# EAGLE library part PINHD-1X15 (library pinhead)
PIN HEADER
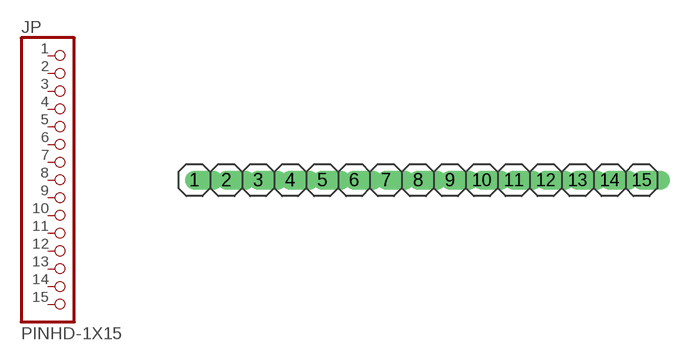
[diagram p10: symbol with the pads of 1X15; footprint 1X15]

Designator prefix JP

## PINHD-1X15  [1X15]
1  1  pas
2  2  pas
3  3  pas
4  4  pas
5  5  pas
6  6  pas
7  7  pas
8  8  pas
9  9  pas
10  10  pas
11  11  pas
12  12  pas
13  13  pas
14  14  pas
15  15  pas

## Footprint 1X15 (pad centres in mm)
PIN HEADER
drill 1.016 offset: 1 -17.78,0; 2 -15.24,0; 3 -12.7,0; 4 -10.16,0; 5 -7.62,0; 6 -5.08,0; 7 -2.54,0; 8 0,0; 9 2.54,0; 10 5.08,0; 11 7.62,0; 12 10.16,0; 13 12.7,0; 14 15.24,0; 15 17.78,0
